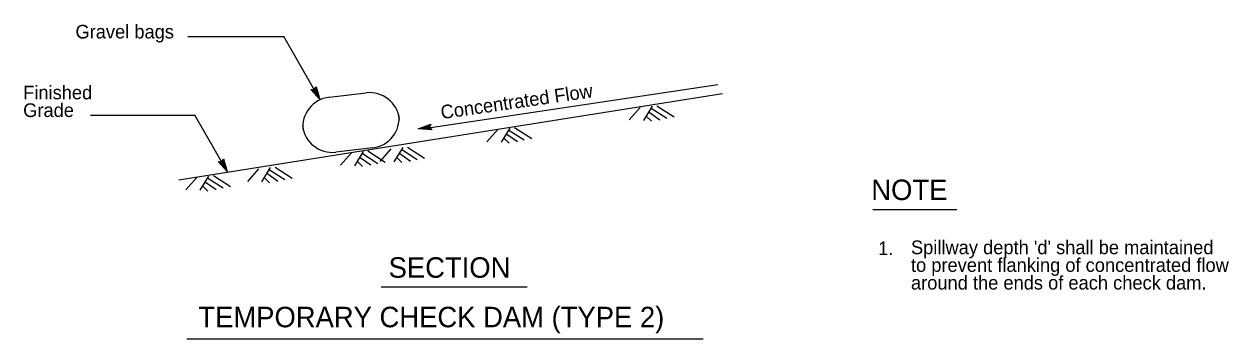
# Model space of a CAD drawing. Extents: x 6707415 to 6708768, y 1869893 to 1870831.
# Drawn here: x 6708219 to 6708748, y 1870583 to 1870721 of the extents above; entities that cross this region are included whole.
import ezdxf

# ---------------------------------------------------------------- set-up
doc = ezdxf.new("R2010")
doc.units = 0
for name, color, linetype in [('56 Stg 3 Anno', 7, 'Continuous'), ('57 Undefined', 7, 'Continuous'), ('58 Soundwalls', 7, 'Continuous'), ('60 Nongeo Data', 7, 'Continuous')]:
    doc.layers.add(name, color=color, linetype=linetype)

msp = doc.modelspace()

# ---------------------------------------------------------------- linework, layer by layer
at = {"layer": '56 Stg 3 Anno'}
for p, q in [((6708290.55, 1870716.08), (6708332.65, 1870716.08)), ((6708348.44, 1870688.27), (6708332.65, 1870716.08)), ((6708346.06, 1870692.66), (6708346.82, 1870693.95)), ((6708346.82, 1870693.95), (6708346.82, 1870693.95)), ((6708346.82, 1870693.95), (6708348.44, 1870688.27)), ((6708523.2, 1870694.75), (6708394.25, 1870675.39)), ((6708348.44, 1870688.27), (6708344.57, 1870692.72)), ((6708344.57, 1870692.72), (6708344.57, 1870692.72)), ((6708344.57, 1870692.72), (6708346.06, 1870692.66)), ((6708347.8, 1870689.44), (6708344.98, 1870692.69)), ((6708347.17, 1870690.6), (6708345.35, 1870692.7)), ((6708346.54, 1870691.77), (6708345.76, 1870692.66)), ((6708346.21, 1870692.93), (6708346.54, 1870691.77)), ((6708346.42, 1870693.24), (6708347.17, 1870690.6)), ((6708346.62, 1870693.6), (6708347.81, 1870689.43)), ((6708348.44, 1870688.27), (6708348.44, 1870688.27)), ((6708247.73, 1870681.52), (6708293.64, 1870681.52)), ((6708307.77, 1870656.63), (6708293.64, 1870681.52)), ((6708391.73, 1870675.39), (6708397.24, 1870677.51)), ((6708397.62, 1870674.97), (6708391.73, 1870675.39)), ((6708391.73, 1870675.39), (6708391.73, 1870675.39)), ((6708397.36, 1870675.28), (6708393.04, 1870675.59)), ((6708393.05, 1870675.59), (6708397.07, 1870677.14)), ((6708394.35, 1870675.78), (6708396.95, 1870676.78)), ((6708397.09, 1870675.59), (6708394.35, 1870675.78)), ((6708395.67, 1870675.98), (6708396.78, 1870676.41)), ((6708396.87, 1870675.89), (6708395.67, 1870675.98)), ((6708397.24, 1870677.51), (6708396.67, 1870676.13)), ((6708396.67, 1870676.13), (6708397.62, 1870674.97)), ((6708397.24, 1870677.51), (6708397.24, 1870677.51)), ((6708397.62, 1870674.97), (6708397.62, 1870674.97)), ((6708305.39, 1870661.01), (6708306.15, 1870662.3)), ((6708306.15, 1870662.3), (6708306.15, 1870662.3)), ((6708306.15, 1870662.3), (6708307.77, 1870656.63)), ((6708307.77, 1870656.63), (6708303.9, 1870661.08)), ((6708303.9, 1870661.08), (6708303.9, 1870661.08)), ((6708303.9, 1870661.08), (6708305.39, 1870661.01)), ((6708307.13, 1870657.8), (6708304.31, 1870661.05)), ((6708306.51, 1870658.96), (6708304.68, 1870661.06)), ((6708305.87, 1870660.12), (6708305.09, 1870661.02)), ((6708305.54, 1870661.29), (6708305.87, 1870660.12)), ((6708305.75, 1870661.59), (6708306.51, 1870658.96)), ((6708305.95, 1870661.96), (6708307.14, 1870657.79)), ((6708307.77, 1870656.63), (6708307.77, 1870656.63))]:
    msp.add_line(p, q, dxfattribs=at)
at = {"layer": '57 Undefined'}
for p, q in [((6708591.27, 1870640.04), (6708628.25, 1870640.04)), ((6708375.4, 1870605.96), (6708439.57, 1870605.96)), ((6708290.12, 1870583.14), (6708516.83, 1870583.14))]:
    msp.add_line(p, q, dxfattribs=at)
at = {"layer": '58 Soundwalls'}
for p, q in [((6708489.23, 1870684.81), (6708484.36, 1870679.33)), ((6708494.39, 1870685.39), (6708490.58, 1870679.15)), ((6708494.05, 1870684.48), (6708500.8, 1870680.14)), ((6708496.49, 1870685.61), (6708504.04, 1870680.76)), ((6708491.82, 1870680.96), (6708494.07, 1870678.77)), ((6708493.12, 1870682.77), (6708497.76, 1870679.44)), ((6708426.72, 1870675.21), (6708421.85, 1870669.73)), ((6708431.88, 1870675.78), (6708428.07, 1870669.55)), ((6708430.61, 1870673.17), (6708435.25, 1870669.84)), ((6708431.54, 1870674.87), (6708438.29, 1870670.54)), ((6708433.98, 1870676.01), (6708441.52, 1870671.16)), ((6708386.96, 1870667.43), (6708394.5, 1870662.58)), ((6708429.31, 1870671.35), (6708431.56, 1870669.17)), ((6708362.36, 1870664.93), (6708357.5, 1870659.44)), ((6708367.53, 1870665.5), (6708363.72, 1870659.26)), ((6708366.25, 1870662.88), (6708370.9, 1870659.56)), ((6708367.19, 1870664.59), (6708373.93, 1870660.26)), ((6708369.62, 1870665.72), (6708377.17, 1870660.87)), ((6708379.7, 1870666.63), (6708374.83, 1870661.15)), ((6708384.86, 1870667.21), (6708381.05, 1870660.97)), ((6708382.28, 1870662.78), (6708384.54, 1870660.59)), ((6708383.58, 1870664.59), (6708388.23, 1870661.26)), ((6708384.52, 1870666.3), (6708391.26, 1870661.96)), ((6708321.54, 1870657.82), (6708316.67, 1870652.33)), ((6708326.71, 1870658.39), (6708322.89, 1870652.15)), ((6708326.37, 1870657.48), (6708333.11, 1870653.15)), ((6708328.8, 1870658.62), (6708336.35, 1870653.77)), ((6708364.95, 1870661.07), (6708367.2, 1870658.89)), ((6708294.46, 1870654.12), (6708289.59, 1870648.64)), ((6708299.62, 1870654.69), (6708295.81, 1870648.46)), ((6708298.34, 1870652.08), (6708302.99, 1870648.75)), ((6708299.28, 1870653.79), (6708306.02, 1870649.45)), ((6708301.72, 1870654.92), (6708309.26, 1870650.07)), ((6708324.13, 1870653.96), (6708326.38, 1870651.78)), ((6708325.43, 1870655.78), (6708330.08, 1870652.45)), ((6708297.04, 1870650.26), (6708299.3, 1870648.08))]:
    msp.add_line(p, q, dxfattribs=at)
at = {"layer": '60 Nongeo Data'}
msp.add_line((6708525.38, 1870690.89), (6708286.58, 1870652.87), dxfattribs=at)
for points in [[(6708352.6, 1870689.32), (6708368.85, 1870691.25)], [(6708371.71, 1870667.14), (6708355.46, 1870665.21)]]:
    msp.add_lwpolyline(points, dxfattribs=at)
for centre, start, end in [((6708354.15, 1870676.27), 96.7672, 186.7672), ((6708370.4, 1870678.2), 6.7672, 96.7672), ((6708370.16, 1870680.19), 276.7672, 6.7672), ((6708353.91, 1870678.26), 186.7672, 276.7672)]:
    msp.add_arc(centre, 13.14, start, end, dxfattribs=at)

# ---------------------------------------------------------------- texts
at = {"layer": '57 Undefined'}
for s, height, p in [('Gravel bags', 6, (6708241.16, 1870715.15)), ('Finished', 6, (6708218.2, 1870688.41)), ('Grade', 6, (6708218.2, 1870680.64)), ('NOTE', 9, (6708590.67, 1870644.15)), ('1.', 6, (6708593.69, 1870619.95)), ("Spillway depth 'd' shall be maintained", 6, (6708608.09, 1870620.37)), ('SECTION', 9, (6708378.68, 1870610.02)), ('to prevent flanking of concentrated flow', 6, (6708608.09, 1870612.61)), ('around the ends of each check dam.', 6, (6708608.09, 1870604.84)), ('TEMPORARY CHECK DAM (TYPE 2)', 9, (6708295.13, 1870588.26))]:
    msp.add_text(s, height=height, dxfattribs=at).set_placement(p)
msp.add_text('Concentrated Flow', height=6, rotation=8.2138, dxfattribs=at).set_placement((6708401.99, 1870679.69))

doc.saveas('drawing.dxf')
